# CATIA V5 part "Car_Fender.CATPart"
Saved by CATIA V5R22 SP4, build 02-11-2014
Part number: Car_Fender
Material "なし"
Bounding box of the stored display mesh (mm): x -800 to 0, y -40 to 122.298, z 0 to 580
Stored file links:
  C:\DATA\Car_ASSY\教育モデル\1_BAS\Car_Fender.CATPart
  C:\DATA\Car_ASSY\Car_Fender.CATPart
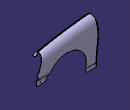
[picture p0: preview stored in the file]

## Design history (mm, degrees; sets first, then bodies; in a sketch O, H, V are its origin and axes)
Set1
  Plane1: type Offset, RefPlane yz-plane, Offset 400, reversed
  Plane2: type Offset, RefPlane Plane1, Offset 400, reversed
Body1 (main body)
  Body2
    Sketch1 on yz-plane, origin (0, 0, 0), H (0, 1, 0), V (0, 0, 1)
      point P4 (100, 50)
      point P5 (10, 450)
      spline S1 through (10, 450) (100, 50)
      line L1 (0, 450) -> (10, 450)
      line L2 (0, 0) -> (0, 450)
      line L3 (100, 0) -> (0, 0)
      line L4 (100, 50) -> (100, 0)
      point P6 (100, 50)
      point P7 (10, 450)
      distance P4 L3 = 50
      distance P5 L2 = 10
      distance L4 L2 = 100
      distance L1 H = 450
      coincidence: L2 V, H L3, P4 P6, P7 P5
    Sketch2 on Plane1, origin (-400, 0, 0), H (0, 1, 0), V (0, 0, 1)
      point P4 (100, 50)
      point P5 (10, 530)
      spline S1 through (10, 530) (100, 50)
      line L1 (0, 530) -> (10, 530)
      line L2 (0, 0) -> (0, 530)
      line L3 (100, 0) -> (0, 0)
      line L4 (100, 50) -> (100, 0)
      point P6 (100, 50)
      point P7 (10, 530)
      distance P4 L3 = 50
      distance P5 L2 = 10
      distance L4 L2 = 100
      distance L1 H = 530
      coincidence: L2 V, H L3, P4 P6, P7 P5
    Sketch3 on Plane2, origin (-800, 0, 0), H (0, 1, 0), V (0, 0, 1)
      point P4 (100, 50)
      point P5 (10, 580)
      spline S1 through (10, 580) (100, 50)
      line L1 (0, 580) -> (10, 580)
      line L2 (0, 0) -> (0, 580)
      line L3 (100, 0) -> (0, 0)
      line L4 (100, 50) -> (100, 0)
      point P6 (100, 50)
      point P7 (10, 580)
      distance P4 L3 = 50
      distance P5 L2 = 10
      distance L4 L2 = 100
      distance L1 H = 580
      coincidence: L2 V, H L3, P4 P6, P7 P5
    Loft1: solid, Sections (Sketch1; Sketch2; Sketch3)
    Body3
      Sketch4 on zx-plane, origin (0, 0, 0), H (-1, 0, 0), V (0, 0, 1)
        line L1 (-46.4952, 240) -> (159.0779, 240)
        arc A1 centre (390, 110) radius 265 from (159.0779, 240) to (655, 109.9999) cw
        point P2 (390, 110)
        line L2 (655, 109.9999) -> (655, -30)
        line L3 (-46.4952, 626.6258) -> (850, 626.6258)
        line L4 (850, 626.6258) -> (850, -30)
        line L5 (850, -30) -> (655, -30)
        line L6 (-46.4952, 626.6258) -> (-46.4952, 240)
        radius A1 = 265
        distance P2 H = 110
        distance V P2 = 390
        distance H L1 = 240
        horizontal: L1 H, L3 H, L5 H
        tangency: L2 A1
        vertical: L2 V, L4 V, L6 V
      Pad1: profile Sketch4, direction (0, 1, 0), length 340, mirrored extent
    Intersect1: tool Body3
    Shell1: ExtOffset 0, Face (face of Loft1; face of Pad1 from Sketch4.A1; face of Pad1 from Sketch4.L1; face of Loft1; face of Loft1; face of Loft1), IntOffset 3
    Sketch5 on Plane2, origin (-800, 0, 0), H (0, 1, 0), V (0, 0, 1)
      line L1 (0, 580) -> (0, 545)
      line L2 (-5, 540) -> (-40, 540)
      point P2 (-40, 540)
      reference projected line E1 (10, 580) -> (0, 580)
      reference intersected line E2 (0, 0) -> (0, 580)
      arc A1 centre (-5, 545) radius 5 from (-5, 540) to (0, 545) ccw
      line L3 (-5, 537) -> (-40, 537)
      arc A2 centre (-5, 545) radius 8 from (-5, 537) to (3, 545) ccw
      line L4 (3, 580) -> (3, 545)
      line L5 (-40, 537) -> (-40, 540)
      line L6 (3, 580) -> (0, 580)
      reference projected line E3 (10, 580) -> (0, 580)
      distance E1 L2 = 40
      radius A1 = 5
      distance L1 P2 = 40
      length L5 = 3
      length L6 = 3
      radius A2 = 8
      vertical: L1 V, L4 V, L5 V
      horizontal: L2 H, L6 H, L3 H
      coincidence: L1 E2, L6 E3
      tangency: A1 L2, A1 L1, L4 A2, A2 L3
    Rib1: profile Sketch5, centre curve edge [face of Loft1 | face of Loft1]
    Sketch6 on Plane2, origin (-800, 0, 0), H (0, 1, 0), V (0, 0, 1)
      projected curve E1 from edge [face of Shell1 | face of Rib1]
      projected line E2 (10, 576.9862) -> (3, 576.9862) from edge [face of Shell1 | face of Rib1]
      point P4 (3, 576.9862)
      projected line E3 (3, 576.9862) -> (3, 545) from edge [face of Rib1 | face of Rib1]
      projected line E4 (3, 576.9862) -> (3, 399.233) from edge [face of Rib1 | face of Rib1]
      point P5 (3, 576.9862)
      projected line E5 (97, 0) -> (97, 50) from edge [face of Shell1 | face of Rib1]
      line L1 (97, 0) -> (37, 0)
      line L2 (37, 0) -> (17.9077, 155.4943)
      arc A1 centre (2003, 399.233) radius 2000 from (3, 399.233) to (17.9077, 155.4943) ccw
      angle L1 L2 = 97
      length L1 = 60
      radius A1 = 2000
      horizontal: L1 H
      tangency: A1 E3, A1 L2
      coincidence: P4 P5
    Pad2: profile Sketch6, direction (1, 0, 0), length 10, opposite side length -7
    Sketch7 on yz-plane, origin (0, 0, 0), H (0, 1, 0), V (0, 0, 1)
      projected curve E1 from edge [face of Loft1 | face of Shell1]
      projected curve E2 from edge [face of Loft1 | face of Shell1]
      point P1 (103.8705, 240)
      line L1 (100.927, 243) -> (92.1161, 243)
      line L2 (86.1161, 237) -> (86.1161, 160)
      line L3 (86.1161, 160) -> (89.1161, 160)
      line L4 (89.1161, 160) -> (89.1161, 237)
      point P5 (103.8705, 240)
      line L5 (101.1109, 260) -> (104.111, 260)
      point P6 (101.1109, 260)
      point P7 (104.111, 260)
      offset curve E3 from edge [face of Loft1 | face of Shell1]
      offset curve E4 from edge [face of Loft1 | face of Shell1]
      line L6 (92.1161, 240) -> (103.8705, 240)
      arc A1 centre (92.1161, 237) radius 3 from (92.1161, 240) to (89.1161, 237) ccw
      arc A2 centre (92.1161, 237) radius 6 from (92.1161, 243) to (86.1161, 237) ccw
      distance L4 L2 = 3
      distance L4 E1 = 15
      distance L1 L6 = 3
      radius A1 = 3
      radius A2 = 6
      distance L6 L3 = 80
      distance L5 L6 = 20
      horizontal: L1 H, L3 H, L5 H, L6 H
      vertical: L2 V, L4 V
      coincidence: P7 E1, E3 P6, P6 L5, P7 L5, P5 P1
      tangency: A1 L6, A1 L4, A2 L1, A2 L2
    Rib2: profile Sketch7, centre curve edge [face of Pad1 from Sketch4.L1 | face of Shell1]
    Body4
      Sketch8 on zx-plane, origin (0, 0, 0), H (-1, 0, 0), V (0, 0, 1)
        point P1 (0, 300)
        line L1 (0, 300) -> (127.0171, 520)
        line L2 (127.0171, 520) -> (-100, 520)
        line L3 (-100, 520) -> (-100, 300)
        line L4 (-100, 300) -> (0, 300)
        angle L1 L4 = 120
        distance L4 H = 300
        coincidence: P1 V
        horizontal: L2 H, L4 H
        vertical: L3 V
      Pad3: profile Sketch8, direction (0, 1, 0), length 220, mirrored extent
    Remove1: tool Body4
    Sketch9 on xy-plane, origin (0, 0, 0), H (1, 0, 0), V (0, 1, 0)
      line L1 (-730, -50.1266) -> (-730, -25)
      arc A1 centre (-725, -25) radius 5 from (-730, -25) to (-720, -25) cw
      point P3 (-725, -25)
      line L2 (-720, -25) -> (-720, -50.1266)
      line L3 (-720, -50.1266) -> (-730, -50.1266)
      reference projected line E1 (-5.7993, -40) -> (-800, -40) from edge [face of Rib1 | face of Rib1]
      reference projected line E2 (-800, -40) -> (-800, -5) from edge [face of Rib1 | face of Rib1]
      radius A1 = 5
      distance P3 E1 = 15
      distance P3 E2 = 75
      vertical: L1 V, L2 V
      tangency: A1 L1, L2 A1
      horizontal: L3 H
    Pocket1: profile Sketch9, direction (0, 0, 1), length 660
    RectPattern1: of Pocket1, direction 1 instances 3, spacing 270, along X axis
    Sketch10 on {plane type Tangent, Support face of Rib2, RefPoint {point type OnSurface, Support face of Rib2, RefPoint {point stored without definition}, Length 0, Direction (0, 0, -1000)}}, origin (-99.3533, 90.7181, 174.1703), H (0.9999, -0.0138, 0), V (0, 0, 1)
      point P1 (49.366, 15.8297)
      reference projected line E1 (99.366, -14.1703) -> (99.366, 62.8297) from edge [face of Rib2 | face of Rib2]
      reference projected line E2 (-59.6229, -14.1703) -> (99.366, -14.1703) from edge [face of Rib2 | face of Rib2]
      distance P1 E1 = 50
      distance P1 E2 = 30
    Hole1: placed by Sketch10, at (-49.9929, 89.9835, 190) direction (-0.016, -0.9999, 0), diameter 15, depth 15
    Chamfer1: length 70, angle 35, on edge [face of Rib2 | face of Rib2]
    Fillet1: radius 10, on edge [face of Rib1 | face of Rib1]; edge [face of Rib1 | face of Pad3 from Sketch8.L1]
    Fillet2: radius 5, on edge [face of Rib2 | face of Chamfer1]; edge [face of Chamfer1 | face of Rib2]; edge [face of Rib2 | face of Rib2]
    Fillet3: radius 10, on edge [face of Pad1 from Sketch4.L2 | face of Pad2]
  Add1: tool Body2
